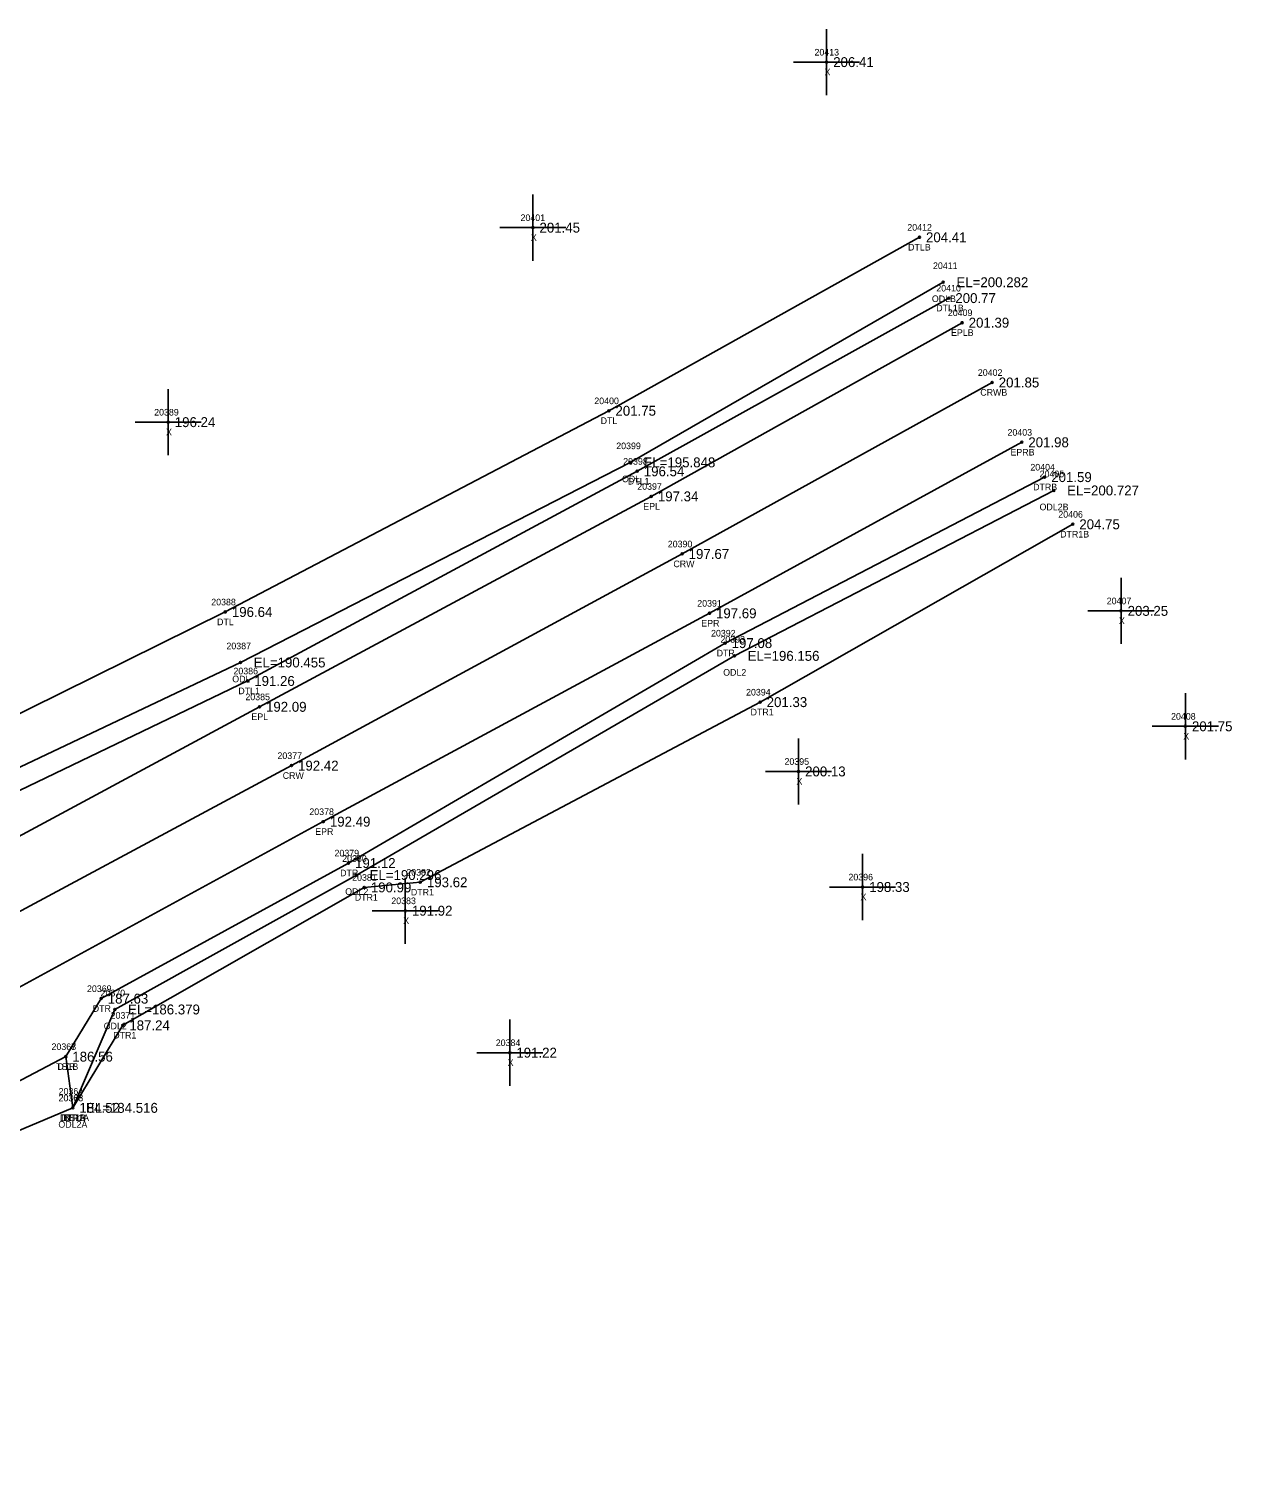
# Model space of a CAD drawing. Extents: x 2279528 to 2280976, y 1061373 to 1062235.
# Drawn here: x 2280793.7 to 2280975.8, y 1062015.3 to 1062235.3 of the extents above; entities that cross this region are included whole.
import ezdxf

# ---------------------------------------------------------------- set-up
doc = ezdxf.new("R2010")
doc.units = 0
for name, color, linetype in [('RD_DTM_BkLn1', 7, 'Continuous'), ('RD_DTM_BkLn2', 7, 'Continuous'), ('RD_DTM_BkLn_txCode', 7, 'Continuous'), ('RD_EX_H2O', 7, 'Continuous'), ('RD_EX_H2O_txCode', 7, 'Continuous'), ('RD_EX_Misc', 7, 'Continuous'), ('RD_EX_Misc_txCode', 7, 'Continuous'), ('RD_EX_Road', 7, 'Continuous'), ('RD_EX_Road_txCode', 7, 'Continuous'), ('RD_EX_TX_H2O_ELEV', 7, 'Continuous'), ('RD_EX_TX_Misc_ELEV', 7, 'Continuous'), ('RD_EX_TX_Road_ELEV', 7, 'Continuous'), ('RD_HC_Survey_ELEV', 7, 'Continuous'), ('RD_HC_Survey_txCode', 7, 'Continuous'), ('RD_SMD_Locator', 7, 'Continuous')]:
    doc.layers.add(name, color=color, linetype=linetype)

msp = doc.modelspace()

# ---------------------------------------------------------------- linework, layer by layer
at = {"layer": 'RD_DTM_BkLn1'}
msp.add_lwpolyline([(2279559.79, 1061433.13), (2279641.23, 1061477.49), (2279727.93, 1061524.84), (2279814.76, 1061571.75), (2279901.26, 1061618.64), (2279982.8, 1061662.56), (2280064.7, 1061706.86), (2280148.08, 1061751.86), (2280234.22, 1061798.46), (2280310.96, 1061840.01), (2280397.69, 1061887.57), (2280487.27, 1061936.5), (2280573.03, 1061983.12), (2280654.64, 1062027.66), (2280741.28, 1062074.45), (2280833.39, 1062123.87), (2280892.52, 1062155.9), (2280939.46, 1062181.85)], dxfattribs=at)
at = {"layer": 'RD_DTM_BkLn2'}
for points in [[(2280272.88, 1061795.9), (2280297.58, 1061791.78), (2280309.49, 1061810.68), (2280320.64, 1061820.76), (2280406.65, 1061872.9), (2280496.79, 1061919.98), (2280582.43, 1061964.41), (2280663.95, 1062011.32), (2280685.25, 1062021.45), (2280750.74, 1062056.04), (2280766.13, 1062062.47), (2280799.22, 1062079.83)], [(2280270.02, 1061790.74), (2280279.94, 1061788.98), (2280298.7, 1061789.36), (2280312.74, 1061804.74), (2280323.13, 1061815.81), (2280411.42, 1061866.03), (2280499.93, 1061915.08), (2280584.56, 1061957.49), (2280666.91, 1062006.18), (2280674.46, 1062011.72), (2280685.18, 1062009.25), (2280689.93, 1062011.32), (2280693.25, 1062019.83), (2280753.26, 1062052.49), (2280766.38, 1062057.83), (2280800.29, 1062072.08)]]:
    msp.add_lwpolyline(points, dxfattribs=at)
at = {"layer": 'RD_EX_H2O'}
for points in [[(2280671.49, 1062066.28), (2280729.4, 1062100.68), (2280823.37, 1062147.12), (2280881.44, 1062177.57), (2280928.45, 1062203.82)], [(2280674.72, 1062065.62), (2280732.53, 1062095.36), (2280825.67, 1062139.48), (2280884.68, 1062169.76), (2280932.06, 1062197.02)], [(2280671.49, 1062066.28), (2280674.44, 1062061.98), (2280733.82, 1062092.04), (2280826.76, 1062136.68), (2280885.73, 1062168.41), (2280932.89, 1062194.62)], [(2280800.29, 1062072.08), (2280799.22, 1062079.83), (2280804.58, 1062088.61), (2280842.02, 1062109.13), (2280899.03, 1062142.41), (2280947.41, 1062167.53)], [(2280800.29, 1062072.08), (2280806.66, 1062086.97), (2280843.22, 1062107.31), (2280900.45, 1062140.48), (2280948.81, 1062165.51)], [(2280800.29, 1062072.08), (2280807.85, 1062084.57), (2280844.41, 1062105.44), (2280852.9, 1062106.22), (2280904.33, 1062133.48), (2280951.66, 1062160.39)]]:
    msp.add_lwpolyline(points, dxfattribs=at)
at = {"layer": 'RD_EX_Misc'}
for p, q in [((2280914.4, 1062225.33), (2280914.4, 1062235.33)), ((2280909.4, 1062230.33), (2280919.4, 1062230.33)), ((2280869.94, 1062200.28), (2280869.94, 1062210.28)), ((2280864.94, 1062205.28), (2280874.94, 1062205.28)), ((2280814.73, 1062170.85), (2280814.73, 1062180.85)), ((2280809.73, 1062175.85), (2280819.73, 1062175.85)), ((2280958.97, 1062142.29), (2280958.97, 1062152.29)), ((2280953.97, 1062147.29), (2280963.97, 1062147.29)), ((2280968.71, 1062124.82), (2280968.71, 1062134.82)), ((2280963.71, 1062129.82), (2280973.71, 1062129.82)), ((2280910.15, 1062117.99), (2280910.15, 1062127.99)), ((2280905.15, 1062122.99), (2280915.15, 1062122.99)), ((2280919.85, 1062100.5), (2280919.85, 1062110.5)), ((2280850.63, 1062096.91), (2280850.63, 1062106.91)), ((2280914.85, 1062105.5), (2280924.85, 1062105.5)), ((2280845.63, 1062101.91), (2280855.63, 1062101.91)), ((2280866.44, 1062075.43), (2280866.44, 1062085.43)), ((2280861.44, 1062080.43), (2280871.44, 1062080.43))]:
    msp.add_line(p, q, dxfattribs=at)
at = {"layer": 'RD_EX_Road'}
for points in [[(2279554.31, 1061441.46), (2279636.61, 1061486.51), (2279673.46, 1061506.76), (2279683.06, 1061512.21), (2279723.14, 1061533.54), (2279809.28, 1061580.29), (2279896.91, 1061627.91), (2279977.07, 1061671.02), (2280059.64, 1061715.57), (2280142.91, 1061760.72), (2280228.83, 1061807.06), (2280306.04, 1061849.18), (2280392.98, 1061896.71), (2280482.82, 1061945.75), (2280567.83, 1061991.78), (2280649.94, 1062036.55), (2280660.56, 1062042.19), (2280676.12, 1062050.66), (2280737.28, 1062083.64), (2280828.54, 1062132.77), (2280887.86, 1062164.61), (2280934.91, 1062190.9)], [(2280403.05, 1061879.04), (2280492, 1061927.92), (2280577.25, 1061974.17), (2280660.08, 1062018.91), (2280745.99, 1062065.19), (2280838.21, 1062115.39), (2280896.66, 1062146.92), (2280943.94, 1062172.8)]]:
    msp.add_lwpolyline(points, dxfattribs=at)
at = {"layer": 'RD_SMD_Locator'}
for centre in [(2280914.4, 1062230.33), (2280869.94, 1062205.28), (2280928.45, 1062203.82), (2280932.06, 1062197.02), (2280932.89, 1062194.62), (2280934.91, 1062190.9), (2280939.46, 1062181.85), (2280881.44, 1062177.57), (2280814.73, 1062175.85), (2280943.94, 1062172.8), (2280884.68, 1062169.76), (2280885.73, 1062168.41), (2280947.41, 1062167.53), (2280887.86, 1062164.61), (2280948.81, 1062165.51), (2280951.66, 1062160.39), (2280892.52, 1062155.9), (2280823.37, 1062147.12), (2280896.66, 1062146.92), (2280958.97, 1062147.29), (2280899.03, 1062142.41), (2280900.45, 1062140.48), (2280825.67, 1062139.48), (2280826.76, 1062136.68), (2280904.33, 1062133.48), (2280828.54, 1062132.77), (2280968.71, 1062129.82), (2280833.39, 1062123.87), (2280910.15, 1062122.99), (2280838.21, 1062115.39), (2280842.02, 1062109.13), (2280843.22, 1062107.31), (2280844.41, 1062105.44), (2280852.9, 1062106.22), (2280919.85, 1062105.5), (2280850.63, 1062101.91), (2280804.58, 1062088.61), (2280806.66, 1062086.97), (2280807.85, 1062084.57), (2280799.22, 1062079.83), (2280799.22, 1062079.83), (2280866.44, 1062080.43), (2280800.29, 1062072.08), (2280800.29, 1062072.08), (2280800.29, 1062072.08), (2280800.29, 1062072.08)]:
    msp.add_circle(centre, 0.15, dxfattribs=at)

# ---------------------------------------------------------------- texts
at = {"layer": 'RD_DTM_BkLn_txCode'}
for s, p in [('20368', (2280797.07, 1062080.83)), ('TS1B', (2280797.78, 1062077.83)), ('20363', (2280798.15, 1062073.08)), ('BS1B', (2280798.87, 1062070.08))]:
    msp.add_text(s, height=1, dxfattribs=at).set_placement(p)
at = {"layer": 'RD_EX_H2O_txCode'}
for s, p in [('20412', (2280926.62, 1062204.82)), ('DTLB', (2280926.74, 1062201.82)), ('20411', (2280930.51, 1062199.02)), ('20410', (2280931.01, 1062195.62)), ('ODLB', (2280930.34, 1062194.02)), ('DTL1B', (2280931, 1062192.62)), ('20400', (2280879.24, 1062178.57)), ('DTL', (2280880.2, 1062175.57)), ('20399', (2280882.56, 1062171.76)), ('20398', (2280883.61, 1062169.41)), ('20404', (2280945.25, 1062168.53)), ('ODL', (2280883.43, 1062166.76)), ('DTL1', (2280884.32, 1062166.41)), ('20405', (2280946.65, 1062167.51)), ('DTRB', (2280945.67, 1062165.53)), ('ODL2B', (2280946.64, 1062162.51)), ('20406', (2280949.48, 1062161.39)), ('DTR1B', (2280949.76, 1062158.39)), ('20388', (2280821.25, 1062148.12)), ('DTL', (2280822.13, 1062145.12)), ('20387', (2280823.55, 1062141.48)), ('20392', (2280896.91, 1062143.41)), ('20393', (2280898.33, 1062142.48)), ('DTR', (2280897.76, 1062140.41)), ('20386', (2280824.61, 1062137.68)), ('ODL2', (2280898.75, 1062137.48)), ('ODL', (2280824.43, 1062136.48)), ('DTL1', (2280825.35, 1062134.68)), ('20394', (2280902.21, 1062134.48)), ('DTR1', (2280902.9, 1062131.48)), ('20379', (2280839.91, 1062110.13)), ('20380', (2280841.07, 1062109.31)), ('DTR', (2280840.76, 1062107.13)), ('20381', (2280842.58, 1062106.44)), ('20382', (2280850.78, 1062107.22)), ('ODL2', (2280841.53, 1062104.31)), ('DTR1', (2280851.47, 1062104.22)), ('DTR1', (2280842.98, 1062103.44)), ('20369', (2280802.44, 1062089.61)), ('20370', (2280804.5, 1062088.97)), ('DTR', (2280803.31, 1062086.61)), ('20371', (2280806.02, 1062085.57)), ('ODL2', (2280804.97, 1062083.97)), ('DTR1', (2280806.42, 1062082.57)), ('20367', (2280797.07, 1062080.83)), ('DTR', (2280797.95, 1062077.83)), ('20364', (2280798.15, 1062074.08)), ('20366', (2280798.13, 1062073.08)), ('20365', (2280798.15, 1062073.08)), ('ODL2A', (2280798.11, 1062069.08)), ('DTR1A', (2280798.37, 1062070.08)), ('DTRA', (2280798.53, 1062070.08))]:
    msp.add_text(s, height=1, dxfattribs=at).set_placement(p)
at = {"layer": 'RD_EX_Misc_txCode'}
for s, p in [('20413', (2280912.57, 1062231.33)), ('X', (2280914.09, 1062228.33)), ('20401', (2280868.07, 1062206.28)), ('X', (2280869.63, 1062203.28)), ('20389', (2280812.61, 1062176.85)), ('X', (2280814.41, 1062173.85)), ('20407', (2280956.81, 1062148.29)), ('X', (2280958.65, 1062145.29)), ('20408', (2280966.55, 1062130.82)), ('X', (2280968.4, 1062127.82)), ('20395', (2280908.03, 1062123.99)), ('X', (2280909.84, 1062120.99)), ('20396', (2280917.71, 1062106.5)), ('20383', (2280848.51, 1062102.91)), ('X', (2280919.54, 1062103.5)), ('X', (2280850.31, 1062099.91)), ('20384', (2280864.32, 1062081.43)), ('X', (2280866.12, 1062078.43))]:
    msp.add_text(s, height=1, dxfattribs=at).set_placement(p)
at = {"layer": 'RD_EX_Road_txCode'}
for s, p in [('20409', (2280932.76, 1062191.9)), ('EPLB', (2280933.24, 1062188.9)), ('20403', (2280941.79, 1062173.8)), ('EPRB', (2280942.24, 1062170.8)), ('20397', (2280885.74, 1062165.61)), ('EPL', (2280886.65, 1062162.61)), ('20391', (2280894.82, 1062147.92)), ('EPR', (2280895.43, 1062144.92)), ('20385', (2280826.42, 1062133.77)), ('EPL', (2280827.33, 1062130.77)), ('20378', (2280836.1, 1062116.39)), ('EPR', (2280836.99, 1062113.39))]:
    msp.add_text(s, height=1, dxfattribs=at).set_placement(p)
at = {"layer": 'RD_EX_TX_H2O_ELEV'}
for s, p in [('204.41', (2280929.45, 1062203.07)), ('EL=200.282', (2280934.06, 1062196.27)), ('200.77', (2280933.89, 1062193.87)), ('201.75', (2280882.44, 1062176.82)), ('EL=195.848', (2280886.68, 1062169.01)), ('196.54', (2280886.73, 1062167.66)), ('201.59', (2280948.41, 1062166.78)), ('EL=200.727', (2280950.81, 1062164.76)), ('204.75', (2280952.66, 1062159.64)), ('196.64', (2280824.37, 1062146.37)), ('197.08', (2280900.03, 1062141.66)), ('EL=190.455', (2280827.67, 1062138.73)), ('EL=196.156', (2280902.45, 1062139.73)), ('191.26', (2280827.76, 1062135.93)), ('201.33', (2280905.33, 1062132.73)), ('191.12', (2280843.02, 1062108.38)), ('EL=190.296', (2280845.22, 1062106.56)), ('190.99', (2280845.41, 1062104.69)), ('193.62', (2280853.9, 1062105.47)), ('187.63', (2280805.58, 1062087.86)), ('EL=186.379', (2280808.66, 1062086.22)), ('187.24', (2280808.85, 1062083.82)), ('186.56', (2280800.22, 1062079.08)), ('184.52', (2280801.29, 1062071.33)), ('184.52', (2280801.29, 1062071.33)), ('EL=184.516', (2280802.29, 1062071.33))]:
    msp.add_text(s, height=1.5, dxfattribs=at).set_placement(p)
at = {"layer": 'RD_EX_TX_Misc_ELEV'}
for s, p in [('206.41', (2280915.4, 1062229.58)), ('201.45', (2280870.94, 1062204.53)), ('196.24', (2280815.73, 1062175.1)), ('203.25', (2280959.97, 1062146.54)), ('201.75', (2280969.71, 1062129.07)), ('200.13', (2280911.15, 1062122.24)), ('198.33', (2280920.85, 1062104.75)), ('191.92', (2280851.63, 1062101.16)), ('191.22', (2280867.44, 1062079.68)), ('186.56', (2280800.22, 1062079.08)), ('184.52', (2280801.29, 1062071.33))]:
    msp.add_text(s, height=1.5, dxfattribs=at).set_placement(p)
at = {"layer": 'RD_EX_TX_Road_ELEV'}
for s, p in [('201.39', (2280935.91, 1062190.15)), ('201.98', (2280944.94, 1062172.05)), ('197.34', (2280888.86, 1062163.86)), ('197.69', (2280897.66, 1062146.17)), ('192.09', (2280829.54, 1062132.02)), ('192.49', (2280839.21, 1062114.64))]:
    msp.add_text(s, height=1.5, dxfattribs=at).set_placement(p)
at = {"layer": 'RD_HC_Survey_ELEV'}
for s, p in [('201.85', (2280940.46, 1062181.1)), ('197.67', (2280893.52, 1062155.15)), ('192.42', (2280834.39, 1062123.12))]:
    msp.add_text(s, height=1.5, dxfattribs=at).set_placement(p)
at = {"layer": 'RD_HC_Survey_txCode'}
for s, p in [('20402', (2280937.3, 1062182.85)), ('CRWB', (2280937.67, 1062179.85)), ('20390', (2280890.36, 1062156.9)), ('CRW', (2280891.21, 1062153.9)), ('20377', (2280831.27, 1062124.87)), ('CRW', (2280832.07, 1062121.87))]:
    msp.add_text(s, height=1, dxfattribs=at).set_placement(p)

doc.saveas('drawing.dxf')
